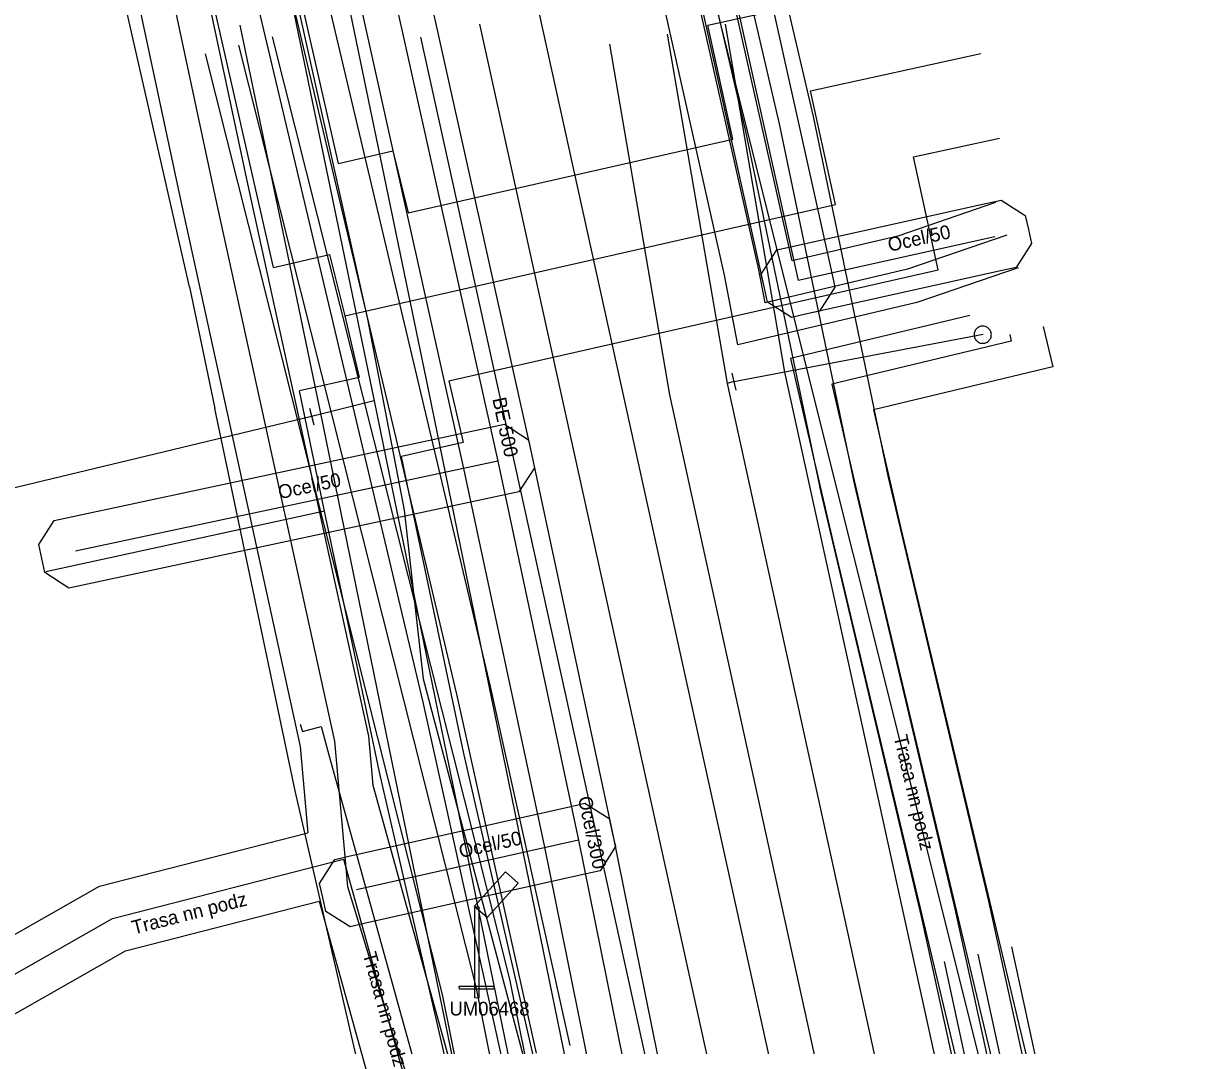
# Model space of a CAD drawing. Extents: x -762993 to -761845, y -975230 to -974501.
# Drawn here: x -762303.15 to -762269.27, y -974947.13 to -974917.56 of the extents above; entities that cross this region are included whole.
import ezdxf

# ---------------------------------------------------------------- set-up
doc = ezdxf.new("R2010")
doc.units = 0
for name, color, linetype in [('IS_CETIN_OP', 7, 'Continuous'), ('IS_CETIN_podzem metalika zam', 7, 'Continuous'), ('IS_CETIN_podzem optika zam', 7, 'Continuous'), ('IS_CETIN_podzem out of order', 7, 'Continuous'), ('IS_CEZ-D_anotace', 7, 'Continuous'), ('IS_CEZ-D_el vedeni NN podzem', 7, 'Continuous'), ('IS_CEZ-D_el vedeni VN podzem', 7, 'Continuous'), ('IS_CEZ-D_OP', 7, 'Continuous'), ('IS_CEZ-T_parovod', 7, 'Continuous'), ('IS_CEZ-T_parovod OP', 7, 'Continuous'), ('IS_DPmUL_OP', 7, 'Continuous'), ('IS_DPmUL_trakce vedeni', 7, 'Continuous'), ('IS_DPmUL_VO lampy', 7, 'Continuous'), ('IS_DPmUL_VO lampy anotace', 7, 'Continuous'), ('IS_DPmUL_VO vedeni podzem', 7, 'Continuous'), ('IS_GASNET_plyn NTL anotace', 7, 'Continuous'), ('IS_GASNET_plyn NTL pripojky', 7, 'Continuous'), ('IS_GASNET_plyn NTL rad', 7, 'Continuous'), ('IS_GASNET_plyn OP', 7, 'Continuous'), ('IS_SCVK_kanalizace anotace', 7, 'Continuous'), ('IS_SCVK_kanalizace jednotna', 7, 'Continuous'), ('IS_SCVK_kanalizace OP', 7, 'Continuous'), ('IS_SCVK_vodovod OP', 7, 'Continuous'), ('IS_SCVK_vodovod pripojky', 7, 'Continuous'), ('IS_SCVK_vodovod privadec', 7, 'Continuous'), ('IS_SCVK_vodovod znaky', 7, 'Continuous'), ('IS_T-Mobile_OP', 7, 'Continuous'), ('IS_T-Mobile_podzem optika', 7, 'Continuous')]:
    doc.layers.add(name, color=color, linetype=linetype)

msp = doc.modelspace()

# ---------------------------------------------------------------- linework, layer by layer
at = {"layer": 'IS_CETIN_OP'}
for points in [[(-762280.893, -974924.427), (-762282.884, -974915.581), (-762284.324, -974909.144), (-762285.833, -974902.246)], [(-762282.467, -974926.853), (-762282.849, -974924.843), (-762284.836, -974916.019), (-762286.276, -974909.576), (-762287.787, -974902.674)], [(-762294.697, -974915.399), (-762289.635, -974936.746), (-762287.334, -974947.134)], [(-762296.643, -974915.861), (-762291.585, -974937.194), (-762289.286, -974947.566)], [(-762275.005, -974922.734), (-762277.838, -974923.708), (-762280.893, -974924.427)], [(-762274.355, -974924.626), (-762277.282, -974925.632), (-762282.467, -974926.853)]]:
    msp.add_lwpolyline(points, dxfattribs=at)
at = {"layer": 'IS_CETIN_podzem metalika zam'}
msp.add_lwpolyline([(-762274.68, -974923.68), (-762277.56, -974924.67), (-762281.68, -974925.64)], dxfattribs=at)
at = {"layer": 'IS_CETIN_podzem optika zam'}
for points in [[(-762281.68, -974925.64), (-762281.87, -974924.64), (-762283.86, -974915.8), (-762285.3, -974909.36), (-762286.81, -974902.46)], [(-762295.67, -974915.63), (-762290.61, -974936.97), (-762288.31, -974947.35)]]:
    msp.add_lwpolyline(points, dxfattribs=at)
at = {"layer": 'IS_CETIN_podzem out of order'}
for points in [[(-762315.54, -974815.74), (-762314.98, -974819.24), (-762313.44, -974828.11), (-762308.35, -974858.04), (-762293.19, -974926.11)], [(-762272.42, -974974.86), (-762270.77, -974967.99), (-762273.36, -974955.96), (-762284.91, -974909.78)], [(-762293.19, -974926.11), (-762292.13, -974931.64), (-762291.58, -974936.52), (-762281.02, -974976.31)]]:
    msp.add_lwpolyline(points, dxfattribs=at)
at = {"layer": 'IS_CEZ-D_el vedeni NN podzem'}
for points in [[(-762274.596, -974926.558), (-762274.55, -974926.753), (-762279.742, -974927.991), (-762278.721, -974932.399), (-762273.265, -974955.317), (-762272.945, -974957.326)], [(-762295.143, -974937.829), (-762295.076, -974938.05), (-762294.535, -974937.897), (-762294.283, -974938.826), (-762290.474, -974952.526), (-762291.051, -974952.674), (-762291.561, -974952.805), (-762291.611, -974952.854), (-762292.425, -974953.651), (-762292.054, -974954.011)], [(-762308.766, -974953.887), (-762309.934, -974948.785), (-762300.571, -974943.46), (-762293.885, -974941.744), (-762291.069, -974951.858), (-762290.962, -974952.243), (-762291.763, -974952.443), (-762292.705, -974953.365), (-762292.054, -974954.011)]]:
    msp.add_lwpolyline(points, dxfattribs=at)
at = {"layer": 'IS_CEZ-D_el vedeni VN podzem'}
msp.add_lwpolyline([(-762319.41, -974797.73), (-762319.25, -974811.07), (-762319.17, -974818.56), (-762319.75, -974821.12), (-762319.39, -974827.6), (-762319.57, -974829.15), (-762319.18, -974830.57), (-762316.82, -974835.07), (-762316.02, -974837.94), (-762313.42, -974849.63), (-762312.46, -974854.51), (-762310.64, -974863.67), (-762308.7, -974872.87), (-762307.01, -974881.16), (-762305.95, -974886.26), (-762303.49, -974897.19), (-762302.61, -974900), (-762301.21, -974905.67), (-762297.61, -974922.54), (-762294.15, -974938.33), (-762293.77, -974942.53), (-762292.42, -974946.94), (-762291.37, -974950), (-762286.61, -974971.16)], dxfattribs=at)
at = {"layer": 'IS_CEZ-D_OP'}
msp.add_line((-762293.032, -974939.594), (-762289.666, -974951.7), dxfattribs=at)
for points in [[(-762320.41, -974797.756), (-762320.25, -974811.081), (-762320.171, -974818.453), (-762320.756, -974821.036), (-762320.393, -974827.57), (-762320.586, -974829.228), (-762320.116, -974830.939), (-762317.755, -974835.441), (-762316.99, -974838.183), (-762314.399, -974849.835), (-762313.441, -974854.704), (-762311.62, -974863.871), (-762309.679, -974873.073), (-762307.989, -974881.362), (-762306.927, -974886.472), (-762304.457, -974897.45), (-762303.573, -974900.27), (-762302.185, -974905.894), (-762298.587, -974922.751), (-762295.14, -974938.483), (-762294.915, -974940.976)], [(-762318.41, -974797.704), (-762318.25, -974811.059), (-762318.169, -974818.667), (-762318.744, -974821.204), (-762318.387, -974827.63), (-762318.554, -974829.072), (-762318.244, -974830.201), (-762315.885, -974834.699), (-762315.05, -974837.697), (-762312.441, -974849.425), (-762311.479, -974854.316), (-762309.66, -974863.469), (-762307.721, -974872.667), (-762306.031, -974880.958), (-762304.973, -974886.048), (-762302.523, -974896.93), (-762301.647, -974899.73), (-762300.235, -974905.446), (-762296.633, -974922.329), (-762293.16, -974938.177), (-762293.032, -974939.594)], [(-762275.752, -974926.012), (-762280.94, -974927.249), (-762279.695, -974932.628), (-762274.247, -974955.512), (-762273.933, -974957.483)], [(-762273.623, -974926.328), (-762273.348, -974927.494), (-762278.544, -974928.733), (-762277.747, -974932.17), (-762272.283, -974955.122), (-762271.957, -974957.169)], [(-762309.741, -974954.11), (-762311.075, -974948.283), (-762300.949, -974942.525), (-762294.915, -974940.976)], [(-762307.791, -974953.664), (-762308.793, -974949.287), (-762300.193, -974944.395), (-762294.586, -974942.956), (-762292.201, -974951.522), (-762292.269, -974951.539), (-762294.13, -974953.36), (-762292.758, -974954.721)]]:
    msp.add_lwpolyline(points, dxfattribs=at)
at = {"layer": 'IS_CEZ-T_parovod'}
msp.add_line((-762294.43, -974931.67), (-762302.5, -974933.43), dxfattribs=at)
for points in [[(-762295.91, -974924.62), (-762301.02, -974902.17), (-762302.87, -974893.94), (-762306.09, -974879.58), (-762309.21, -974865.52), (-762309.51, -974864.27)], [(-762293.85, -974926.02), (-762279.64, -974922.8), (-762280.36, -974919.51), (-762275.43, -974918.43)], [(-762295.91, -974924.62), (-762294.29, -974924.24), (-762293.85, -974926.02), (-762293.43, -974927.8), (-762295.16, -974928.19)], [(-762283.42, -974980.17), (-762292.84, -974939.22), (-762294.43, -974931.67), (-762295.16, -974928.19)]]:
    msp.add_lwpolyline(points, dxfattribs=at)
at = {"layer": 'IS_CEZ-T_parovod OP'}
msp.add_line((-762298.348, -974925.175), (-762297.607, -974928.703), dxfattribs=at)
for points in [[(-762294.031, -974921.611), (-762298.582, -974901.618), (-762300.431, -974893.392), (-762303.65, -974879.036), (-762306.774, -974864.957), (-762307.079, -974863.687)], [(-762298.348, -974925.175), (-762303.458, -974902.722), (-762305.309, -974894.488), (-762308.53, -974880.124), (-762311.646, -974866.083), (-762311.941, -974864.853)], [(-762292.011, -974923.04), (-762282.613, -974920.91), (-762283.337, -974917.603), (-762275.965, -974915.988)], [(-762290.838, -974927.901), (-762276.667, -974924.69), (-762277.383, -974921.417), (-762274.895, -974920.872)], [(-762294.031, -974921.611), (-762292.456, -974921.242), (-762292.011, -974923.04)], [(-762290.838, -974927.901), (-762290.417, -974929.683), (-762292.208, -974930.087)], [(-762285.856, -974980.73), (-762295.282, -974939.758), (-762296.877, -974932.184), (-762297.607, -974928.703)], [(-762281.54, -974977.193), (-762290.398, -974938.682), (-762291.983, -974931.156), (-762292.208, -974930.087)]]:
    msp.add_lwpolyline(points, dxfattribs=at)
at = {"layer": 'IS_DPmUL_OP'}
for p, q in [((-762295.95, -974917.946), (-762289.08, -974945.211)), ((-762297.89, -974918.434), (-762291.032, -974945.653))]:
    msp.add_line(p, q, dxfattribs=at)
for points in [[(-762258.333, -974977.451), (-762258.911, -974976.857), (-762264.915, -974977.224), (-762266.907, -974977.291), (-762267.513, -974975.869), (-762269.198, -974969.908), (-762270.652, -974963.384), (-762273.142, -974952.356), (-762275.203, -974942.951), (-762278.102, -974930.696), (-762280.281, -974920.247), (-762281.475, -974915.132), (-762281.962, -974913.124), (-762282.189, -974912.029), (-762283.754, -974904.594), (-762284.925, -974900.109), (-762286.219, -974894.21), (-762287.471, -974887.789), (-762288.305, -974884.361), (-762293.731, -974861.088), (-762293.932, -974860.117)], [(-762260.681, -974978.969), (-762264.821, -974979.222), (-762268.209, -974979.335), (-762269.403, -974976.537), (-762271.138, -974970.398), (-762272.604, -974963.822), (-762275.094, -974952.79), (-762277.153, -974943.395), (-762280.054, -974931.13), (-762282.235, -974920.679), (-762283.421, -974915.594), (-762283.914, -974913.562), (-762284.147, -974912.437), (-762285.702, -974905.052), (-762286.871, -974900.577), (-762288.177, -974894.616), (-762289.425, -974888.217), (-762290.251, -974884.825), (-762295.685, -974861.518), (-762295.891, -974860.523)], [(-762289.08, -974945.211), (-762282.713, -974976.79), (-762282.434, -974980.657), (-762284.649, -974984.068)], [(-762291.032, -974945.653), (-762284.699, -974977.06), (-762284.478, -974980.131), (-762286.443, -974983.158)]]:
    msp.add_lwpolyline(points, dxfattribs=at)
at = {"layer": 'IS_DPmUL_trakce vedeni'}
msp.add_lwpolyline([(-762245.348, -974993.683), (-762251.428, -974985.673), (-762257.908, -974979.323), (-762259.308, -974977.883), (-762264.868, -974978.223), (-762267.558, -974978.313), (-762268.458, -974976.203), (-762270.168, -974970.153), (-762271.628, -974963.603), (-762274.118, -974952.573), (-762276.178, -974943.173), (-762279.078, -974930.913), (-762281.258, -974920.463), (-762282.448, -974915.363), (-762282.938, -974913.343), (-762283.168, -974912.233), (-762284.728, -974904.823), (-762285.898, -974900.343), (-762287.198, -974894.413), (-762288.448, -974888.003), (-762289.278, -974884.593), (-762294.708, -974861.303), (-762294.911, -974860.32)], dxfattribs=at)
at = {"layer": 'IS_DPmUL_VO lampy'}
for points in [[(-762289.196, -974942.102), (-762288.826, -974942.432), (-762289.726, -974943.432), (-762290.106, -974943.112)], [(-762290.086, -974943.112), (-762289.966, -974943.122), (-762289.966, -974945.762), (-762290.086, -974945.752)], [(-762290.536, -974945.412), (-762289.536, -974945.412), (-762289.536, -974945.502), (-762290.526, -974945.502)]]:
    msp.add_lwpolyline(points, close=True, dxfattribs=at)
at = {"layer": 'IS_DPmUL_VO vedeni podzem'}
for points in [[(-762296.92, -974918.19), (-762290.056, -974945.432)], [(-762290.056, -974945.432), (-762283.706, -974976.925), (-762283.456, -974980.394), (-762285.546, -974983.613)]]:
    msp.add_lwpolyline(points, dxfattribs=at)
at = {"layer": 'IS_GASNET_plyn NTL pripojky'}
for points in [[(-762275.031, -974923.734), (-762280.722, -974924.998)], [(-762289.42, -974930.22), (-762301.645, -974932.829)], [(-762287.08, -974941.19), (-762293.51, -974942.63)]]:
    msp.add_lwpolyline(points, dxfattribs=at)
at = {"layer": 'IS_GASNET_plyn NTL rad'}
for points in [[(-762295.02, -974905.04), (-762285.61, -974903), (-762285.41, -974903.9), (-762280.722, -974924.998)], [(-762295.286, -974903.832), (-762295.02, -974905.04), (-762289.42, -974930.22), (-762287.08, -974941.19), (-762280.44, -974973.98), (-762280.33, -974974.5), (-762280.19, -974975.19), (-762279.98, -974976.04), (-762279.87, -974976.51)]]:
    msp.add_lwpolyline(points, dxfattribs=at)
at = {"layer": 'IS_GASNET_plyn OP'}
for points in [[(-762288.137, -974902.525), (-762285.306, -974902.007), (-762284.724, -974902.38), (-762284.634, -974902.783), (-762284.434, -974903.683), (-762279.746, -974924.781), (-762279.656, -974925.185), (-762280.101, -974925.884), (-762280.505, -974925.974), (-762280.909, -974926.064), (-762281.608, -974925.619), (-762281.698, -974925.215), (-762286.37, -974904.188), (-762294.808, -974906.017), (-762295.213, -974906.105), (-762295.909, -974905.657), (-762295.997, -974905.252), (-762296.085, -974904.847), (-762295.637, -974904.151), (-762295.232, -974904.063)], [(-762295.996, -974905.256), (-762296.27, -974904.012), (-762294.302, -974903.652), (-762294.044, -974904.824), (-762288.443, -974930.007), (-762286.101, -974940.986), (-762279.461, -974973.777), (-762279.351, -974974.297), (-762279.214, -974974.971), (-762279.008, -974975.806), (-762278.896, -974976.282), (-762278.802, -974976.685), (-762279.239, -974977.39), (-762279.642, -974977.484), (-762280.045, -974977.578), (-762280.75, -974977.141), (-762280.844, -974976.738), (-762280.952, -974976.274), (-762281.166, -974975.409), (-762281.309, -974974.703), (-762281.419, -974974.183), (-762288.059, -974941.394), (-762290.397, -974930.433)], [(-762274.41, -974924.62), (-762274.814, -974924.71), (-762280.505, -974925.974), (-762280.909, -974926.064), (-762281.608, -974925.619), (-762281.698, -974925.215), (-762281.788, -974924.811), (-762281.343, -974924.112), (-762280.939, -974924.022), (-762275.248, -974922.758), (-762274.844, -974922.668), (-762274.145, -974923.113), (-762274.055, -974923.517), (-762273.965, -974923.921)], [(-762288.806, -974931.111), (-762289.211, -974931.198), (-762301.436, -974933.807), (-762301.841, -974933.894), (-762302.536, -974933.443), (-762302.623, -974933.038), (-762302.71, -974932.633), (-762302.259, -974931.938), (-762301.854, -974931.851), (-762289.629, -974929.242), (-762289.224, -974929.155), (-762288.529, -974929.606), (-762288.442, -974930.011), (-762288.355, -974930.416)], [(-762286.457, -974942.075), (-762286.861, -974942.166), (-762293.291, -974943.606), (-762293.695, -974943.696), (-762294.395, -974943.253), (-762294.486, -974942.849), (-762294.576, -974942.445), (-762294.133, -974941.745), (-762293.729, -974941.654), (-762287.299, -974940.214), (-762286.895, -974940.124), (-762286.195, -974940.567), (-762286.104, -974940.971), (-762286.014, -974941.375)]]:
    msp.add_lwpolyline(points, close=True, dxfattribs=at)
at = {"layer": 'IS_SCVK_kanalizace jednotna'}
msp.add_lwpolyline([(-762282.203, -974952.631), (-762289.938, -974917.573)], dxfattribs=at)
at = {"layer": 'IS_SCVK_kanalizace OP'}
for points in [[(-762280.494, -974952.254), (-762288.229, -974917.196)], [(-762283.912, -974953.008), (-762291.647, -974917.95)]]:
    msp.add_lwpolyline(points, dxfattribs=at)
at = {"layer": 'IS_SCVK_vodovod OP'}
for points in [[(-762293.748, -974916.96), (-762291.431, -974928.152), (-762279.692, -974985.479)], [(-762296.882, -974917.608), (-762294.565, -974928.798), (-762283.191, -974984.34)], [(-762282.833, -974917.58), (-762281.112, -974927.652), (-762268.54, -974984.934)], [(-762286.185, -974918.152), (-762284.45, -974928.304), (-762271.86, -974985.662)]]:
    msp.add_lwpolyline(points, dxfattribs=at)
at = {"layer": 'IS_SCVK_vodovod pripojky'}
for points in [[(-762282.588, -974927.921), (-762275.368, -974926.55)], [(-762292.998, -974928.475), (-762294.809, -974928.932)], [(-762294.809, -974928.932), (-762305.86, -974931.58)]]:
    msp.add_lwpolyline(points, dxfattribs=at)
at = {"layer": 'IS_SCVK_vodovod privadec'}
for points in [[(-762295.315, -974917.284), (-762292.998, -974928.475), (-762281.41, -974985.064)], [(-762284.509, -974917.866), (-762282.781, -974927.978), (-762270.2, -974985.298)]]:
    msp.add_lwpolyline(points, dxfattribs=at)
at = {"layer": 'IS_SCVK_vodovod znaky'}
for points in [[(-762275.529, -974926.365), (-762275.549, -974926.382)], [(-762275.529, -974926.365), (-762275.549, -974926.382)], [(-762275.508, -974926.351), (-762275.529, -974926.365)], [(-762275.508, -974926.351), (-762275.529, -974926.365)], [(-762275.485, -974926.338), (-762275.508, -974926.351)], [(-762275.485, -974926.338), (-762275.508, -974926.351)], [(-762275.461, -974926.329), (-762275.485, -974926.338)], [(-762275.461, -974926.329), (-762275.485, -974926.338)], [(-762275.435, -974926.321), (-762275.461, -974926.329)], [(-762275.435, -974926.321), (-762275.461, -974926.329)], [(-762275.41, -974926.316), (-762275.435, -974926.321)], [(-762275.41, -974926.316), (-762275.435, -974926.321)], [(-762275.384, -974926.314), (-762275.41, -974926.316)], [(-762275.384, -974926.314), (-762275.41, -974926.316)], [(-762275.358, -974926.315), (-762275.384, -974926.314)], [(-762275.358, -974926.315), (-762275.384, -974926.314)], [(-762275.332, -974926.318), (-762275.358, -974926.315)], [(-762275.332, -974926.318), (-762275.358, -974926.315)], [(-762275.306, -974926.324), (-762275.332, -974926.318)], [(-762275.306, -974926.324), (-762275.332, -974926.318)], [(-762275.282, -974926.333), (-762275.306, -974926.324)], [(-762275.282, -974926.333), (-762275.306, -974926.324)], [(-762275.258, -974926.344), (-762275.282, -974926.333)], [(-762275.258, -974926.344), (-762275.282, -974926.333)], [(-762275.236, -974926.358), (-762275.258, -974926.344)], [(-762275.236, -974926.358), (-762275.258, -974926.344)], [(-762275.215, -974926.373), (-762275.236, -974926.358)], [(-762275.215, -974926.373), (-762275.236, -974926.358)], [(-762275.622, -974926.519), (-762275.626, -974926.545)], [(-762275.622, -974926.519), (-762275.626, -974926.545)], [(-762275.626, -974926.545), (-762275.626, -974926.571)], [(-762275.626, -974926.545), (-762275.626, -974926.571)], [(-762275.626, -974926.571), (-762275.623, -974926.597)], [(-762275.626, -974926.571), (-762275.623, -974926.597)], [(-762275.623, -974926.597), (-762275.62, -974926.623)], [(-762275.623, -974926.597), (-762275.62, -974926.623)], [(-762275.617, -974926.493), (-762275.622, -974926.519)], [(-762275.617, -974926.493), (-762275.622, -974926.519)], [(-762275.62, -974926.623), (-762275.612, -974926.648)], [(-762275.62, -974926.623), (-762275.612, -974926.648)], [(-762275.608, -974926.469), (-762275.617, -974926.493)], [(-762275.608, -974926.469), (-762275.617, -974926.493)], [(-762275.612, -974926.648), (-762275.602, -974926.672)], [(-762275.612, -974926.648), (-762275.602, -974926.672)], [(-762275.596, -974926.446), (-762275.608, -974926.469)], [(-762275.596, -974926.446), (-762275.608, -974926.469)], [(-762275.602, -974926.672), (-762275.589, -974926.695)], [(-762275.602, -974926.672), (-762275.589, -974926.695)], [(-762275.583, -974926.423), (-762275.596, -974926.446)], [(-762275.583, -974926.423), (-762275.596, -974926.446)], [(-762275.589, -974926.695), (-762275.574, -974926.717)], [(-762275.589, -974926.695), (-762275.574, -974926.717)], [(-762275.567, -974926.402), (-762275.583, -974926.423)], [(-762275.567, -974926.402), (-762275.583, -974926.423)], [(-762275.549, -974926.382), (-762275.567, -974926.402)], [(-762275.549, -974926.382), (-762275.567, -974926.402)], [(-762275.196, -974926.391), (-762275.215, -974926.373)], [(-762275.196, -974926.391), (-762275.215, -974926.373)], [(-762275.179, -974926.411), (-762275.196, -974926.391)], [(-762275.179, -974926.411), (-762275.196, -974926.391)], [(-762275.186, -974926.726), (-762275.171, -974926.704)], [(-762275.186, -974926.726), (-762275.171, -974926.704)], [(-762275.164, -974926.432), (-762275.179, -974926.411)], [(-762275.164, -974926.432), (-762275.179, -974926.411)], [(-762275.171, -974926.704), (-762275.157, -974926.682)], [(-762275.171, -974926.704), (-762275.157, -974926.682)], [(-762275.151, -974926.455), (-762275.164, -974926.432)], [(-762275.151, -974926.455), (-762275.164, -974926.432)], [(-762275.157, -974926.682), (-762275.145, -974926.659)], [(-762275.157, -974926.682), (-762275.145, -974926.659)], [(-762275.141, -974926.479), (-762275.151, -974926.455)], [(-762275.141, -974926.479), (-762275.151, -974926.455)], [(-762275.145, -974926.659), (-762275.137, -974926.633)], [(-762275.145, -974926.659), (-762275.137, -974926.633)], [(-762275.133, -974926.505), (-762275.141, -974926.479)], [(-762275.133, -974926.505), (-762275.141, -974926.479)], [(-762275.137, -974926.633), (-762275.131, -974926.608)], [(-762275.137, -974926.633), (-762275.131, -974926.608)], [(-762275.129, -974926.53), (-762275.133, -974926.505)], [(-762275.129, -974926.53), (-762275.133, -974926.505)], [(-762275.131, -974926.608), (-762275.128, -974926.582)], [(-762275.131, -974926.608), (-762275.128, -974926.582)], [(-762275.127, -974926.556), (-762275.129, -974926.53)], [(-762275.127, -974926.556), (-762275.129, -974926.53)], [(-762275.128, -974926.582), (-762275.127, -974926.556)], [(-762275.128, -974926.582), (-762275.127, -974926.556)], [(-762275.574, -974926.717), (-762275.557, -974926.736)], [(-762275.574, -974926.717), (-762275.557, -974926.736)], [(-762275.557, -974926.736), (-762275.538, -974926.753)], [(-762275.557, -974926.736), (-762275.538, -974926.753)], [(-762275.538, -974926.753), (-762275.518, -974926.77)], [(-762275.538, -974926.753), (-762275.518, -974926.77)], [(-762275.518, -974926.77), (-762275.495, -974926.784)], [(-762275.518, -974926.77), (-762275.495, -974926.784)], [(-762275.495, -974926.784), (-762275.471, -974926.795)], [(-762275.495, -974926.784), (-762275.471, -974926.795)], [(-762275.471, -974926.795), (-762275.447, -974926.804)], [(-762275.471, -974926.795), (-762275.447, -974926.804)], [(-762275.447, -974926.804), (-762275.421, -974926.809)], [(-762275.447, -974926.804), (-762275.421, -974926.809)], [(-762275.421, -974926.809), (-762275.395, -974926.813)], [(-762275.421, -974926.809), (-762275.395, -974926.813)], [(-762275.395, -974926.813), (-762275.369, -974926.813)], [(-762275.395, -974926.813), (-762275.369, -974926.813)], [(-762275.369, -974926.813), (-762275.344, -974926.811)], [(-762275.369, -974926.813), (-762275.344, -974926.811)], [(-762275.344, -974926.811), (-762275.318, -974926.807)], [(-762275.344, -974926.811), (-762275.318, -974926.807)], [(-762275.318, -974926.807), (-762275.293, -974926.799)], [(-762275.318, -974926.807), (-762275.293, -974926.799)], [(-762275.293, -974926.799), (-762275.269, -974926.789)], [(-762275.293, -974926.799), (-762275.269, -974926.789)], [(-762275.269, -974926.789), (-762275.245, -974926.776)], [(-762275.269, -974926.789), (-762275.245, -974926.776)], [(-762275.245, -974926.776), (-762275.224, -974926.761)], [(-762275.245, -974926.776), (-762275.224, -974926.761)], [(-762275.224, -974926.761), (-762275.204, -974926.744)], [(-762275.224, -974926.761), (-762275.204, -974926.744)], [(-762275.204, -974926.744), (-762275.186, -974926.726)], [(-762275.204, -974926.744), (-762275.186, -974926.726)], [(-762282.645, -974927.677), (-762282.53, -974928.164)], [(-762282.588, -974927.921), (-762282.781, -974927.978)], [(-762294.871, -974928.69), (-762294.748, -974929.174)]]:
    msp.add_lwpolyline(points, dxfattribs=at)
at = {"layer": 'IS_T-Mobile_OP'}
for points in [[(-762272.123, -974955.408), (-762274.534, -974944.274)], [(-762274.077, -974955.832), (-762276.488, -974944.698)]]:
    msp.add_lwpolyline(points, dxfattribs=at)
at = {"layer": 'IS_T-Mobile_podzem optika'}
msp.add_lwpolyline([(-762273.1, -974955.62), (-762275.511, -974944.486)], dxfattribs=at)
msp.add_lwpolyline([(-762273.1, -974955.62), (-762275.511, -974944.486)], dxfattribs=at)

# ---------------------------------------------------------------- texts
at = {"layer": 'IS_CEZ-D_anotace'}
for rotation, p in [(283.3909, (-762277.958, -974938.196)), (14.3915, (-762299.957, -974943.922)), (285.5355, (-762293.333, -974944.485))]:
    msp.add_text('Trasa nn podz', height=0.4, rotation=rotation, dxfattribs=at).set_placement(p)
at = {"layer": 'IS_DPmUL_VO lampy anotace'}
msp.add_text('UM06468', height=0.4, dxfattribs=at).set_placement((-762290.817, -974946.265))
at = {"layer": 'IS_GASNET_plyn NTL anotace'}
for s, rotation, p in [('Ocel/50', 12.5224, (-762278.077, -974924.166)), ('Ocel/50', 12.0471, (-762295.732, -974931.325)), ('Ocel/300', 282.0412, (-762287.099, -974939.963)), ('Ocel/50', 12.6231, (-762290.495, -974941.71))]:
    msp.add_text(s, height=0.4, rotation=rotation, dxfattribs=at).set_placement(p)
at = {"layer": 'IS_SCVK_kanalizace anotace'}
msp.add_text('BE 500', height=0.4, rotation=282, dxfattribs=at).set_placement((-762289.577, -974928.42))

doc.saveas('drawing.dxf')
